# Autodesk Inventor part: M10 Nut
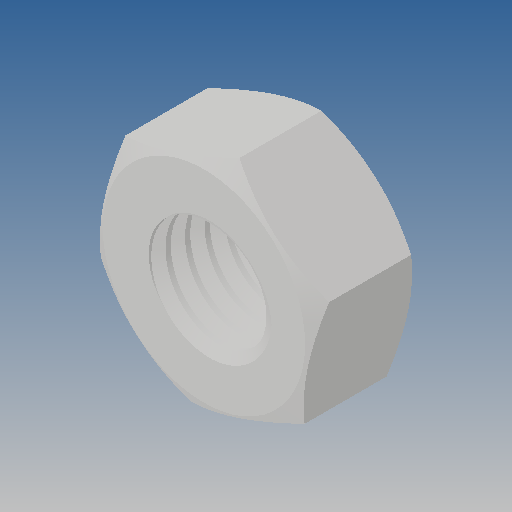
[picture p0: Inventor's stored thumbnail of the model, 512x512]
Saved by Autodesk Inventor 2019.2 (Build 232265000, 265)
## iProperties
Created: 2012-09
Part Number: M10 Nut
Material: Ogólny
Document SubType Name: Modeling
Designer: CADENGINEERING4
Density: 1 g/cm^3
Appearance: Domyślna
Author: CADENGINEERING4
Revision Number: ÈÎºÎ
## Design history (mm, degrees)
feature "ÇÐ³ý-É¨Ãè1"
node "Bryła1"
